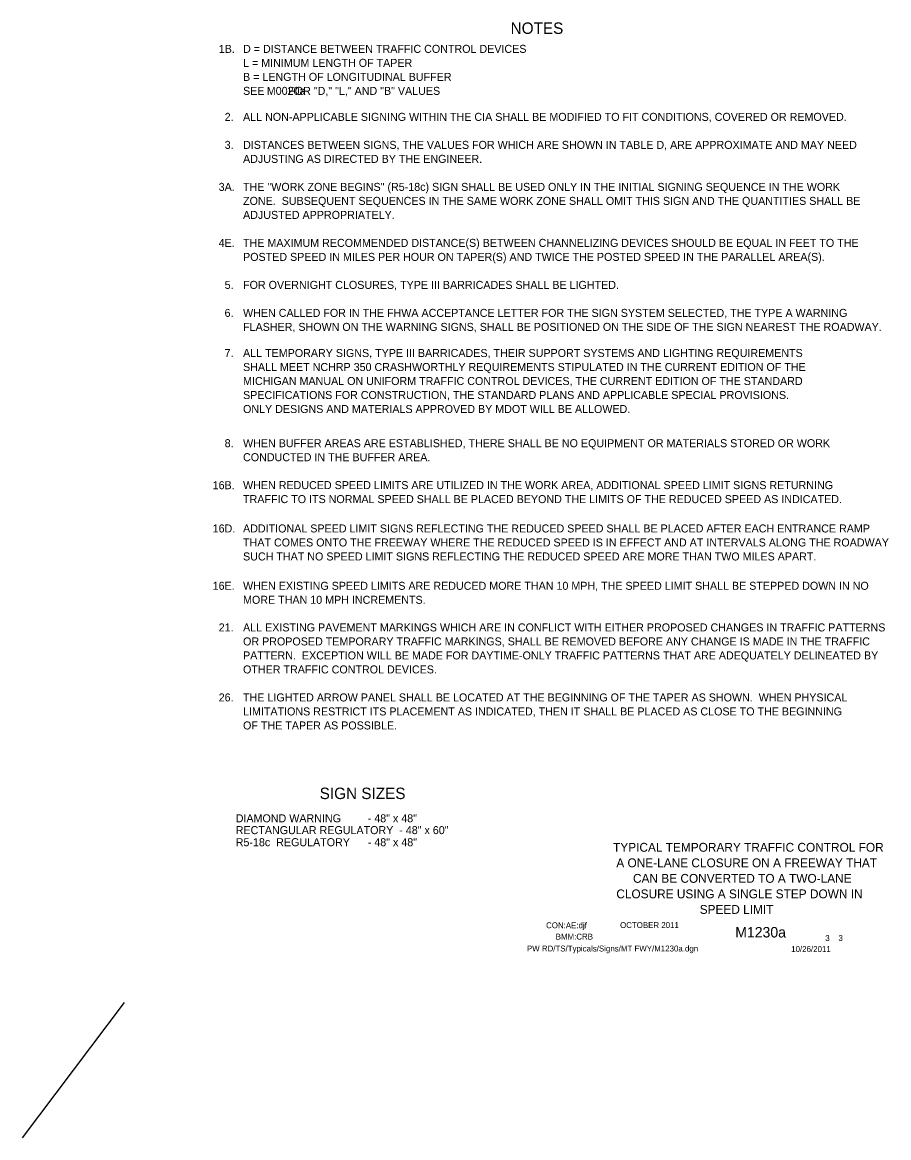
# Model space of a CAD drawing. Extents: x 16576 to 19508, y 5728 to 6974.
# Drawn here: x 18599 to 19508, y 5738 to 6909 of the extents above; entities that cross this region are included whole.
import ezdxf

# ---------------------------------------------------------------- set-up
doc = ezdxf.new("R2010")
doc.units = 0
for name, color, linetype in [('BORDER', 7, 'Continuous'), ('BORDER_SIGNAL_WO', 7, 'Continuous'), ('TYPICAL_TEXT_DIMEN_PR', 7, 'Continuous')]:
    doc.layers.add(name, color=color, linetype=linetype)

msp = doc.modelspace()

# ---------------------------------------------------------------- linework, layer by layer
at = {"layer": 'TYPICAL_TEXT_DIMEN_PR'}
msp.add_line((18705.8, 5880), (18599, 5738.2), dxfattribs=at)

# ---------------------------------------------------------------- texts
at = {"layer": 'BORDER'}
for s, p in [('TYPICAL TEMPORARY TRAFFIC CONTROL FOR', (19219, 6038.4)), ('A ONE-LANE CLOSURE ON A FREEWAY THAT', (19222.4, 6022.1)), ('CAN BE CONVERTED TO A TWO-LANE ', (19239.9, 6005.8)), ('CLOSURE USING A SINGLE STEP DOWN IN ', (19222.4, 5989.5)), ('SPEED LIMIT', (19309.9, 5973.2))]:
    msp.add_text(s, height=9.3, dxfattribs=at).set_placement(p)
at = {"layer": 'BORDER_SIGNAL_WO'}
for s, height, p in [('CON:AE:djf  ', 6.2, (19148.7, 5958.1)), ('    OCTOBER 2011    ', 6.2, (19217.1, 5958.3)), ('BMM:CRB   ', 6.2, (19158.8, 5946.2)), ('    M1230a   ', 11, (19330.9, 5948.4)), (' 3    3 ', 6.2, (19439.4, 5944.7)), ('PW RD/TS/Typicals/Signs/MT FWY/M1230a.dgn      ', 6.2, (19128.6, 5933.7)), ('10/26/2011    ', 6.2, (19405.9, 5933.1))]:
    msp.add_text(s, height=height, dxfattribs=at).set_placement(p)
at = {"layer": 'TYPICAL_TEXT_DIMEN_PR'}
for s, height, p in [('NOTES', 12, (19111.5, 6897)), ('1B.', 8.4, (18805.2, 6877.1)), ('D = DISTANCE BETWEEN TRAFFIC CONTROL DEVICES', 8.4, (18830.7, 6877.1)), ('L = MINIMUM LENGTH OF TAPER', 8.4, (18830.7, 6862.4)), ('B = LENGTH OF LONGITUDINAL BUFFER', 8.4, (18830.7, 6847.7)), ('SEE        FOR "D," "L," AND "B" VALUES', 8.4, (18830.7, 6833)), ('M0020a', 8.4, (18855.6, 6833)), ('2.', 8.4, (18811.4, 6805.7)), ('ALL NON-APPLICABLE SIGNING WITHIN THE CIA SHALL BE MODIFIED TO FIT CONDITIONS, COVERED OR REMOVED.', 8.4, (18830.7, 6805.7)), ('3.', 8.4, (18811.4, 6776.3)), ('DISTANCES BETWEEN SIGNS, THE VALUES FOR WHICH ARE SHOWN IN TABLE D, ARE APPROXIMATE AND MAY NEED', 8.4, (18830.7, 6776.3)), ('ADJUSTING AS DIRECTED BY THE ENGINEER.', 8.4, (18830.7, 6761.6)), ('3A.', 8.4, (18805.1, 6732.2)), ('THE "WORK ZONE BEGINS" (R5-18c) SIGN SHALL BE USED ONLY IN THE INITIAL SIGNING SEQUENCE IN THE WORK', 8.4, (18830.7, 6732.2)), ('ZONE.  SUBSEQUENT SEQUENCES IN THE SAME WORK ZONE SHALL OMIT THIS SIGN AND THE QUANTITIES SHALL BE', 8.4, (18830.7, 6717.5)), ('ADJUSTED APPROPRIATELY.', 8.4, (18830.7, 6702.8)), ('4E.', 8.4, (18805.1, 6673.4)), ('THE MAXIMUM RECOMMENDED DISTANCE(S) BETWEEN CHANNELIZING DEVICES SHOULD BE EQUAL IN FEET TO THE', 8.4, (18830.7, 6673.4)), ('POSTED SPEED IN MILES PER HOUR ON TAPER(S) AND TWICE THE POSTED SPEED IN THE PARALLEL AREA(S).', 8.4, (18830.7, 6658.7)), ('5.', 8.4, (18811.4, 6629.3)), ('FOR OVERNIGHT CLOSURES, TYPE III BARRICADES SHALL BE LIGHTED. ', 8.4, (18830.7, 6629.3)), ('6.', 8.4, (18811.3, 6599.9)), ('WHEN CALLED FOR IN THE FHWA ACCEPTANCE LETTER FOR THE SIGN SYSTEM SELECTED, THE TYPE A WARNING ', 8.4, (18830.7, 6599.9)), ('FLASHER, SHOWN ON THE WARNING SIGNS, SHALL BE POSITIONED ON THE SIDE OF THE SIGN NEAREST THE ROADWAY.', 8.4, (18830.7, 6585.2)), ('7.', 8.4, (18811.3, 6557.8)), ('ALL TEMPORARY SIGNS, TYPE III BARRICADES, THEIR SUPPORT SYSTEMS AND LIGHTING REQUIREMENTS', 8.4, (18830.7, 6557.8)), ('SHALL MEET NCHRP 350 CRASHWORTHLY REQUIREMENTS STIPULATED IN THE CURRENT EDITION OF THE', 8.4, (18830.7, 6543.1)), ('MICHIGAN MANUAL ON UNIFORM TRAFFIC CONTROL DEVICES, THE CURRENT EDITION OF THE STANDARD', 8.4, (18830.7, 6528.4)), ('SPECIFICATIONS FOR CONSTRUCTION, THE STANDARD PLANS AND APPLICABLE SPECIAL PROVISIONS.', 8.4, (18830.7, 6513.7)), ('ONLY DESIGNS AND MATERIALS APPROVED BY MDOT WILL BE ALLOWED.', 8.4, (18830.7, 6499)), ('8.', 8.4, (18811.4, 6463.1)), ('WHEN BUFFER AREAS ARE ESTABLISHED, THERE SHALL BE NO EQUIPMENT OR MATERIALS STORED OR WORK     ', 8.4, (18830.7, 6463.1)), ('CONDUCTED IN THE BUFFER AREA.', 8.4, (18830.7, 6448.4)), ('16B.', 8.4, (18798.8, 6419)), ('WHEN REDUCED SPEED LIMITS ARE UTILIZED IN THE WORK AREA, ADDITIONAL SPEED LIMIT SIGNS RETURNING', 8.4, (18830.7, 6419.1)), ('TRAFFIC TO ITS NORMAL SPEED SHALL BE PLACED BEYOND THE LIMITS OF THE REDUCED SPEED AS INDICATED.', 8.4, (18830.7, 6404.4)), ('16D.', 8.4, (18798.8, 6373.6)), ('ADDITIONAL SPEED LIMIT SIGNS REFLECTING THE REDUCED SPEED SHALL BE PLACED AFTER EACH ENTRANCE RAMP', 8.4, (18830.7, 6373.6)), ('THAT COMES ONTO THE FREEWAY WHERE THE REDUCED SPEED IS IN EFFECT AND AT INTERVALS ALONG THE ROADWAY', 8.4, (18830.7, 6358.9)), ('SUCH THAT NO SPEED LIMIT SIGNS REFLECTING THE REDUCED SPEED ARE MORE THAN TWO MILES APART.', 8.4, (18830.7, 6344.2)), ('16E.', 8.4, (18798.8, 6313.4)), ('WHEN EXISTING SPEED LIMITS ARE REDUCED MORE THAN 10 MPH, THE SPEED LIMIT SHALL BE STEPPED DOWN IN NO', 8.4, (18830.7, 6313.4)), ('MORE THAN 10 MPH INCREMENTS.', 8.4, (18830.7, 6298.7)), ('21.', 8.4, (18805.1, 6269.7)), ('ALL EXISTING PAVEMENT MARKINGS WHICH ARE IN CONFLICT WITH EITHER PROPOSED CHANGES IN TRAFFIC PATTERNS', 8.4, (18830.7, 6269.7)), ('OR PROPOSED TEMPORARY TRAFFIC MARKINGS, SHALL BE REMOVED BEFORE ANY CHANGE IS MADE IN THE TRAFFIC', 8.4, (18830.7, 6255)), ('PATTERN.  EXCEPTION WILL BE MADE FOR DAYTIME-ONLY TRAFFIC PATTERNS THAT ARE ADEQUATELY DELINEATED BY', 8.4, (18830.7, 6240.3)), ('OTHER TRAFFIC CONTROL DEVICES.', 8.4, (18830.7, 6225.6)), ('26.', 8.4, (18805.1, 6196.2)), ('THE LIGHTED ARROW PANEL SHALL BE LOCATED AT THE BEGINNING OF THE TAPER AS SHOWN.  WHEN PHYSICAL', 8.4, (18830.7, 6196.2)), ('LIMITATIONS RESTRICT ITS PLACEMENT AS INDICATED, THEN IT SHALL BE PLACED AS CLOSE TO THE BEGINNING', 8.4, (18830.7, 6181.5)), ('OF THE TAPER AS POSSIBLE.', 8.4, (18830.7, 6166.8)), ('SIGN SIZES', 12, (18911.1, 6093.7)), ('DIAMOND WARNING         - 48" x 48"', 8.4, (18823, 6069.3)), ('RECTANGULAR REGULATORY  - 48" x 60"', 8.4, (18823, 6056.9)), ('R5-18c  REGULATORY      - 48" x 48"', 8.4, (18823, 6044.2))]:
    msp.add_text(s, height=height, dxfattribs=at).set_placement(p)

doc.saveas('drawing.dxf')
